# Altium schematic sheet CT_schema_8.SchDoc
size 226 x 144 mm
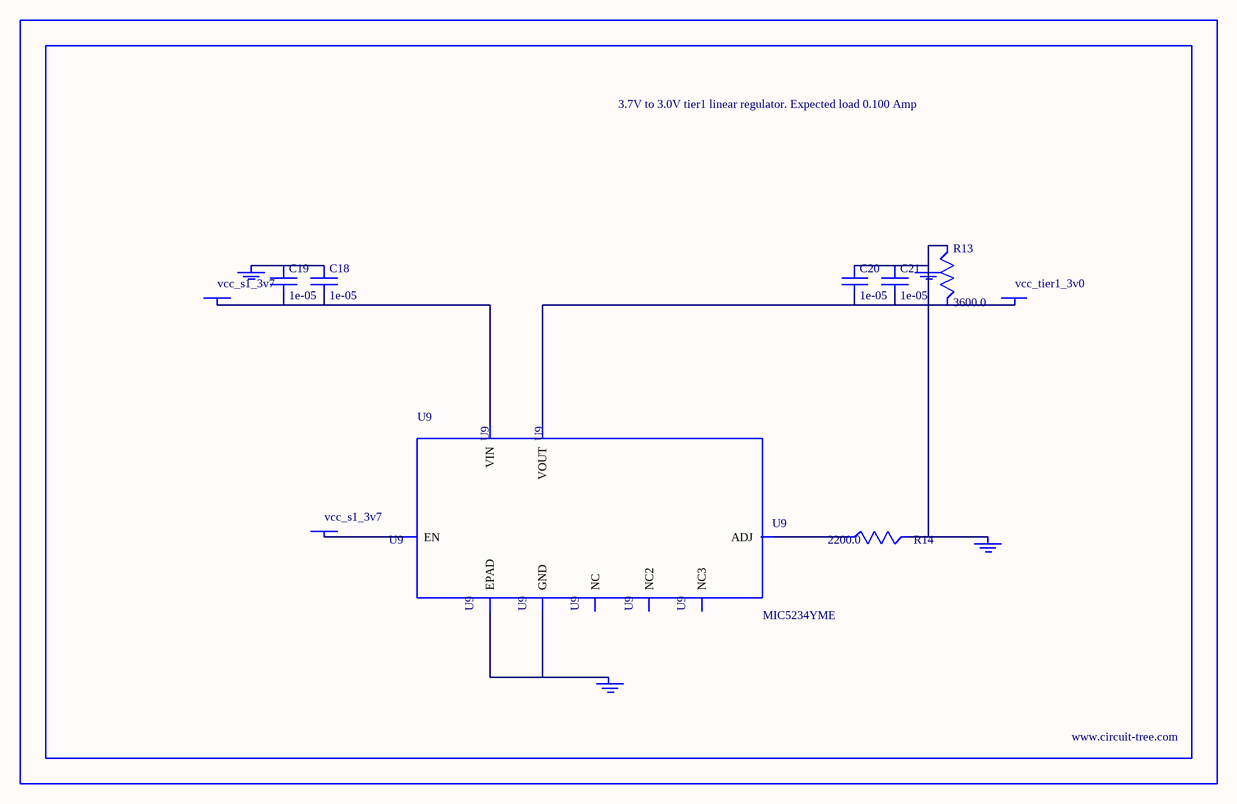
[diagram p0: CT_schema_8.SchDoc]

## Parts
BORDER7  (no value)
C18  1e-05  [C1210]
C19  1e-05  [C1210]
C20  1e-05  [C1210]
C21  1e-05  [C1210]
GND_INSTANCE_7_0  (no value)
GND_INSTANCE_7_1  (no value)
GND_INSTANCE_7_2  (no value)
GND_INSTANCE_7_3  (no value)
POWER_INSTANCE_7_0  vcc_tier1_3v0
POWER_INSTANCE_7_1  vcc_s1_3v7
POWER_INSTANCE_7_2  vcc_s1_3v7
R13  3600.0  [R0603]
R14  2200.0  [R0603]
U9  MIC5234YME  [SOIC-8_EP]

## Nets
NetC18_1: C18.1 C19.1 GND_INSTANCE_7_3.0(GND)
NetC18_2: C18.2 C19.2 POWER_INSTANCE_7_2.0(PWR) U9.8(VIN)
NetC20_1: C20.1 C21.1 GND_INSTANCE_7_0.0(GND) GND_INSTANCE_7_1.0(GND) R13.1 R14.2
NetC20_2: C20.2 C21.2 POWER_INSTANCE_7_0.0(PWR) R13.2 U9.1(VOUT)
NetGND_INSTANCE_7_2_0: GND_INSTANCE_7_2.0(GND) U9.7(GND) U9.EPAD
NetPOWER_INSTANCE_7_1_0: POWER_INSTANCE_7_1.0(PWR) U9.5(EN)
NetR14_1: R14.1 U9.4(ADJ)

Not connected (* = marked no-connect by the designer): U9 2(NC) 3(NC2) 6(NC3)

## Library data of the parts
BORDER7 = BORDER_PAGE7
C18-C21 = C1210C106K5PACTU
GND_INSTANCE_7_0-GND_INSTANCE_7_3 = GND
POWER_INSTANCE_7_0-POWER_INSTANCE_7_2 = PWR
R13 = RC0603JR-073K6L
R14 = RC0603JR-072K2L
